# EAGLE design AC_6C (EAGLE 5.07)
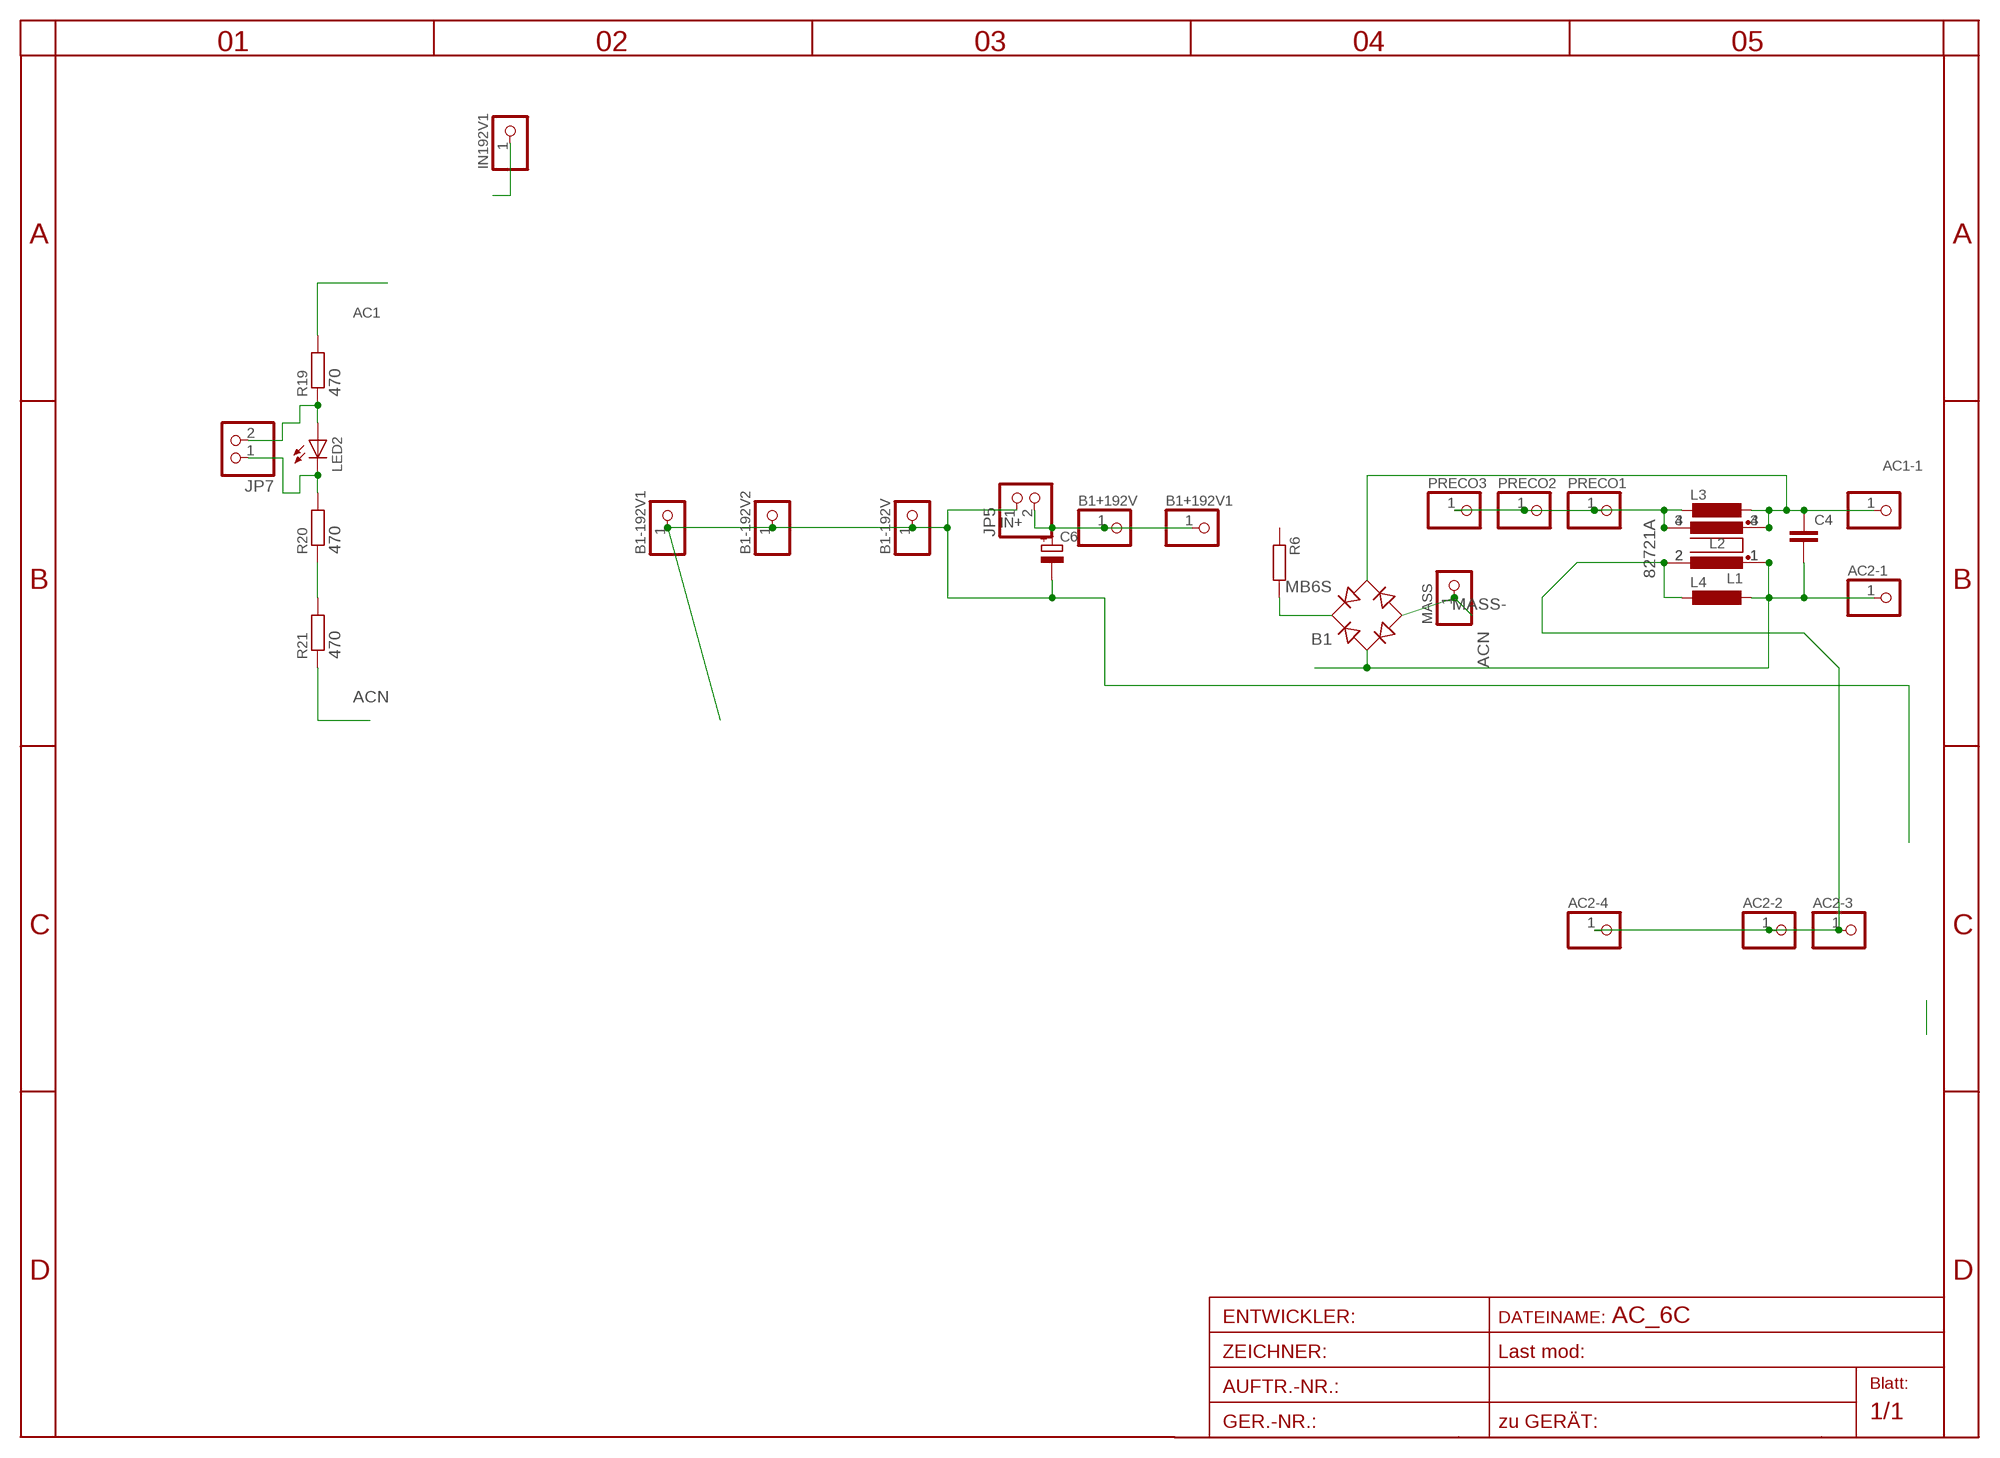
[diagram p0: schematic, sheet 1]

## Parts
AC1-1  PINHD-1X14.5MM  [1X4MM5]
AC2-1  PINHD-1X14.5MM  [1X4MM5]
AC2-2  PINHD-1X13MM2  [1X3MM2]
AC2-3  PINHD-1X13MM2  [1X3MM2]
AC2-4  PINHD-1X12MM3  [1X2MM3]
B1  MB6S  [SOIC-4]
B1+192V  PINHD-1X13MM2  [1X3MM2]
B1+192V1  PINHD-1X13MM2  [1X3MM2]
B1-192V  PINHD-1X13MM2  [1X3MM2]
B1-192V1  PINHD-1X13MM2  [1X3MM2]
B1-192V2  PINHD-1X13MM2  [1X3MM2]
C4  C-EU102-043X133  [C102-043X133]
C6  CPOL-EUE10-20  [EB20D]
IN192V1  PINHD-1X13MM2  [1X3MM2]
JP5  PINHD-1X2STR  [1X02]
JP7  PINHD-1X2STR  [1X02]
L1  R1405VB1  [B1]
L2  82721A  [82721A]
L3  L-EU2200-15.24  [2200-15.24]
L4  L-EU2200-15.24  [2200-15.24]
LED2  LED3MM  [LED3MM]
MASS  PINHD-1X13MM2  [1X3MM2]
PRECO1  PINHD-1X12MM3  [1X2MM3]
PRECO2  PINHD-1X13MM2  [1X3MM2]
PRECO3  PINHD-1X13MM2  [1X3MM2]
R6  R-EU_0207/60  [0207/60]
R19  470  R-EU_0204/5  [0204/5]
R20  470  R-EU_0204/2V  [0204V]
R21  470  R-EU_0204/5  [0204/5]

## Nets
AC1: AC1-1.1 B1.~2(AC2) C4.1 L1.3 L2.4 L3.1 R19.2
ACN: AC2-1.1 B1.~1(AC1) C4.2 L1.1 L2.1 L4.1 R21.1
IN+: B1+192V1.1 B1+192V.1 C6.+ IN192V1.1 JP5.2
INN: AC2-2.1 AC2-3.1 AC2-4.1 L1.2 L2.2 L4.2
MASS-: B1-192V1.1 B1-192V2.1 B1-192V.1 B1.- C6.- JP5.1 MASS.1
N$6: JP7.2 LED2.A R19.1
N$9: JP7.1 LED2.K(C) R20.2
N$13: R20.1 R21.2
N$33: B1.+ R6.2
PRECOIL: L1.4 L2.3 L3.2 PRECO1.1 PRECO2.1 PRECO3.1
Unconnected: R6.1

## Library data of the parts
AC1-1 AC2-1-AC2-4 B1+192V B1+192V1 B1-192V B1-192V1 B1-192V2 IN192V1 MASS PRECO1-PRECO3 = pinhead:PINHD-1X1: PIN HEADER
B1 = rectifier:MB*S: Bridge Rectifier Source: http://www.fairchildsemi.com/ds/MB/MB6S.pdf
C4 = rcl:C-EU: CAPACITOR, European symbol
C6 = rcl:CPOL-EU: POLARIZED CAPACITOR, European symbol
JP5 JP7 = pinhead:PINHD-1X2: PIN HEADER
L1 = inductor-nkl:R1405V: Übertrager (verlustarm) bis typ. 400kHz Power transformer (low loss) up to typ. 400kHz
L2 = inductors:82721A: FILTER
L3 L4 = rcl:L-EU: INDUCTOR, European symbol
LED2 = led:LED: LED
R6 R19-R21 = rcl-2:R-EU_: RESISTOR, European symbol

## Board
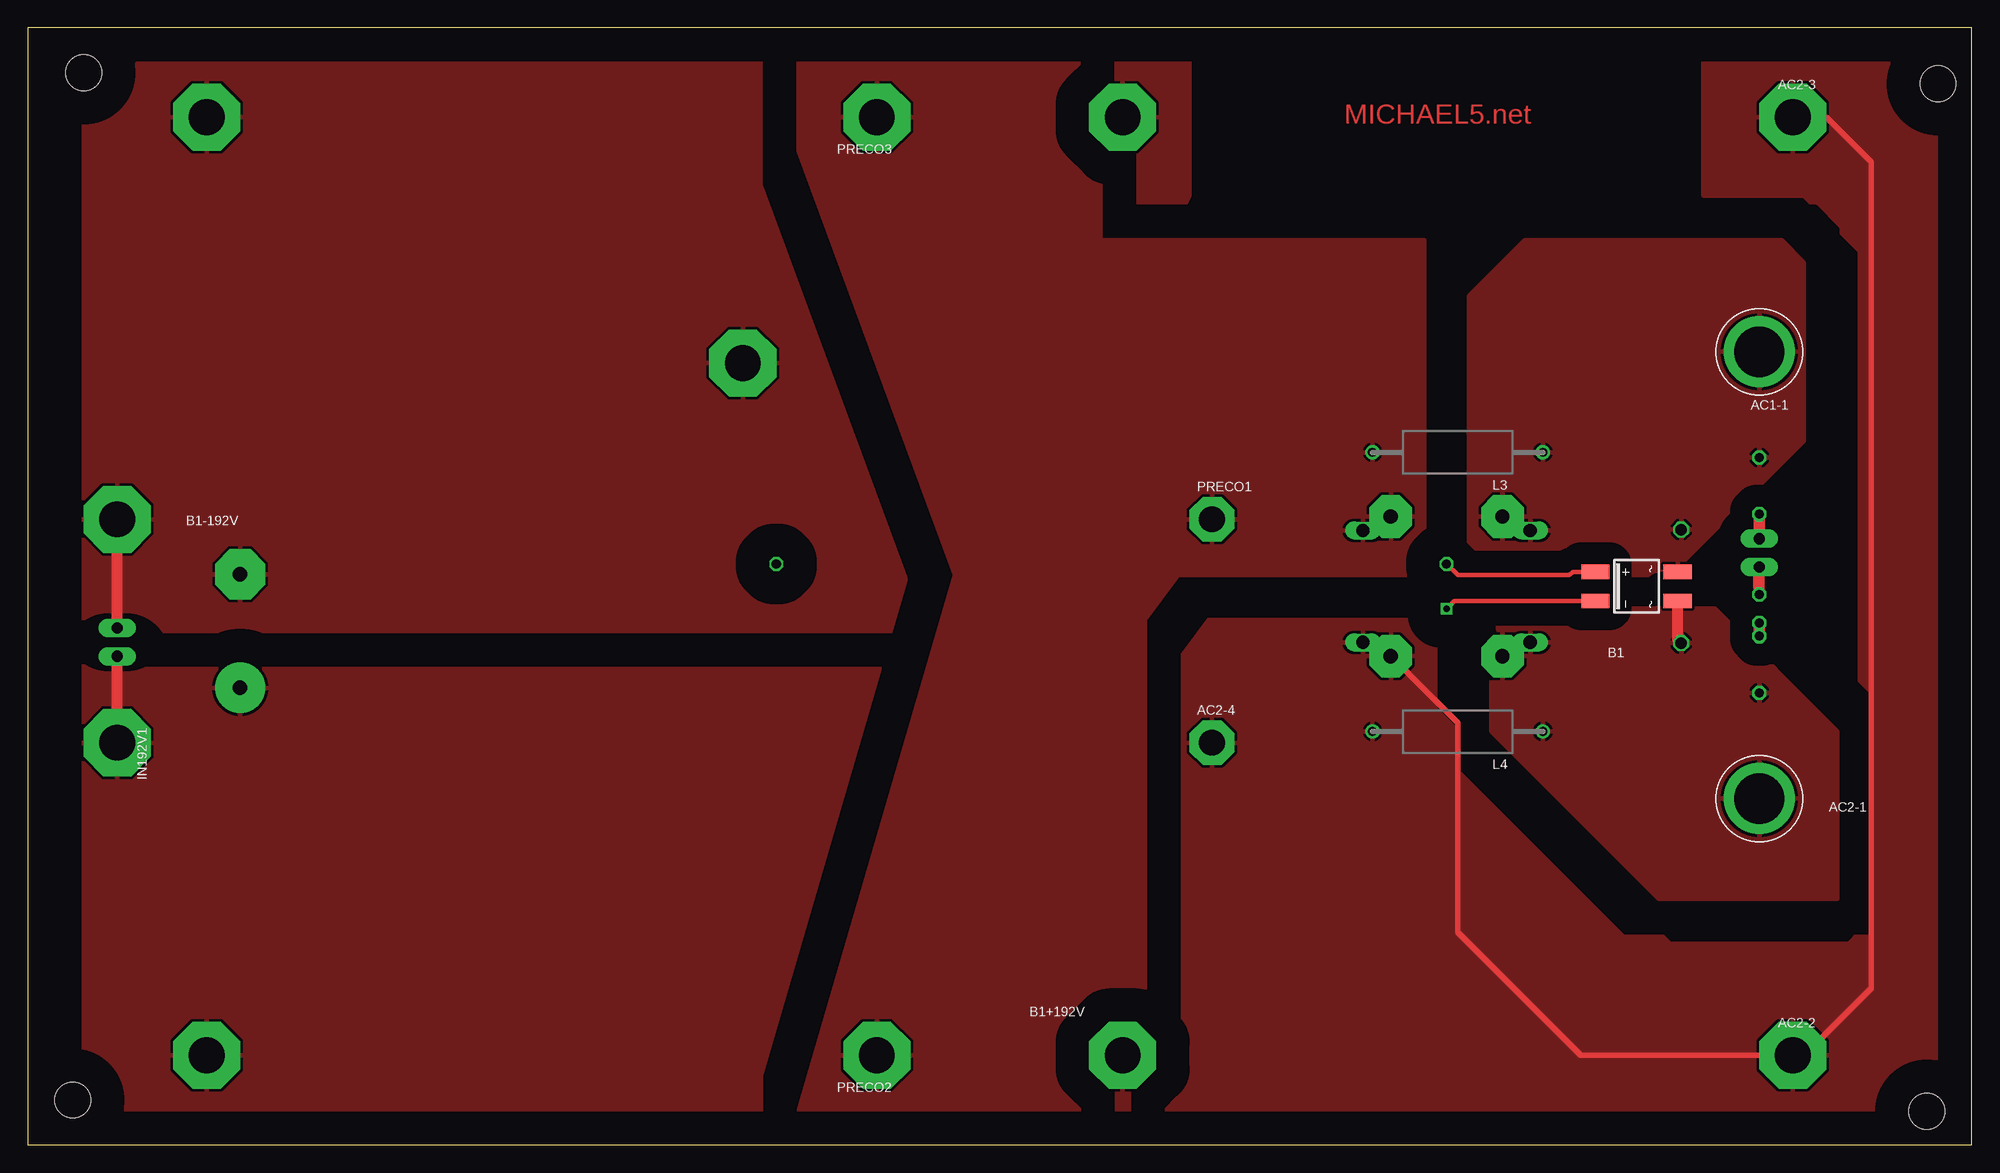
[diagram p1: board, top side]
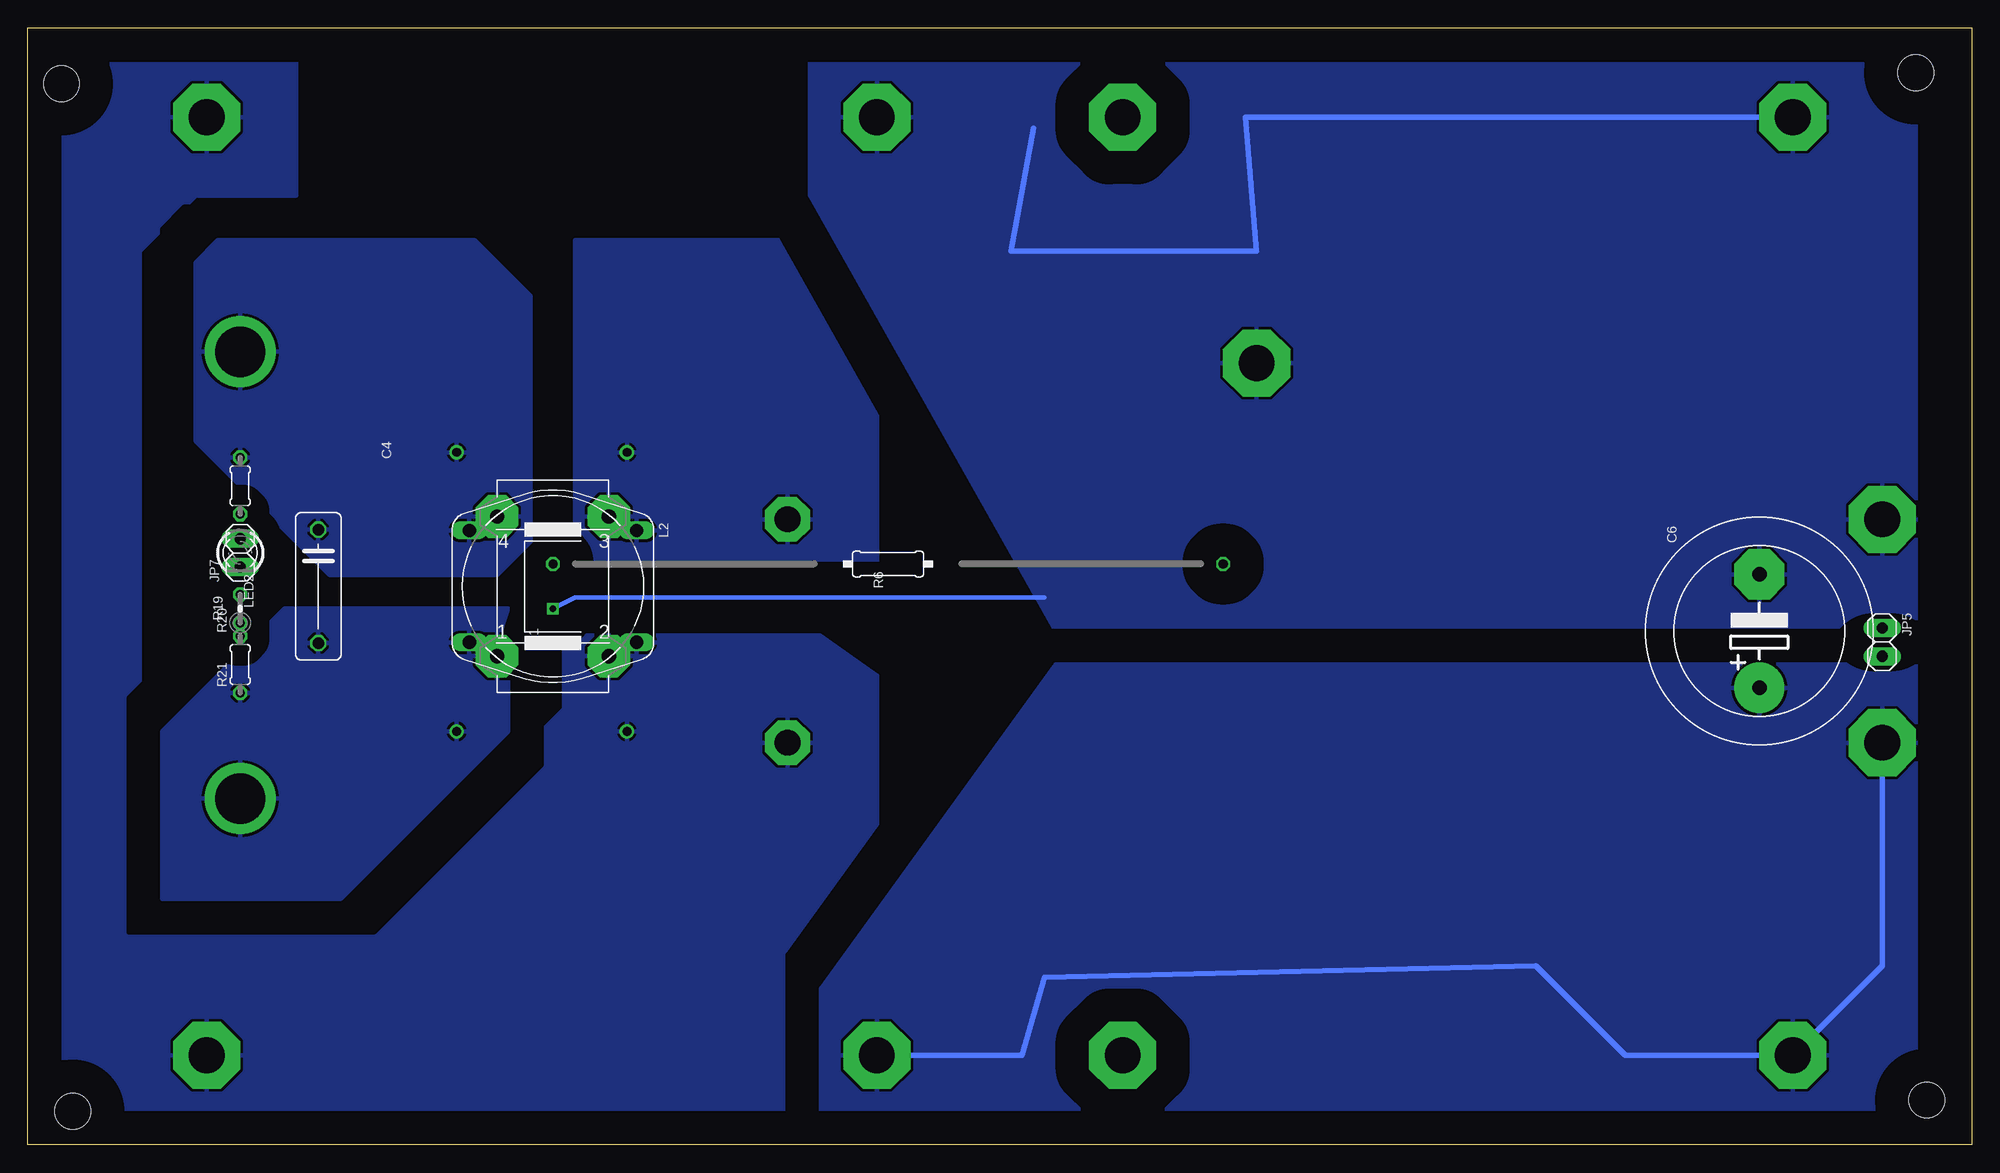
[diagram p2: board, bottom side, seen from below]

Size 174 x 100 mm. Coordinates in mm from the lower left corner, seen from the top.
Outline: 0,0 174,0 174,100 0,100 0,0
Copper layers (1*16): Top 0.035mm / dielectric 1.5mm / Bottom 0.035mm
Design rules "default *": minimum track width 12mil, minimum drill 24mil, track to track 8mil, track to pad 8mil, pad to pad 8mil, via to via 8mil, smd to smd 8mil, copper to edge 40mil, drill to drill 8mil, minimum pad ring 8mil, minimum via ring 8mil, stop-mask expansion 4mil, vias tented up to drill 0mil, thermal gap 10mil
Holes 3.2 mm at 5,96 4,4 171,95 170,3

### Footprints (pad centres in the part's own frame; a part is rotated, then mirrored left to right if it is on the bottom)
1X4MM5 = drill 4.5 pad 6.35 round: 1 0,0
1X3MM2 = drill 3.2 pad 6 octagon: 1 0,0
1X2MM3 = drill 2.3 pad 4 octagon: 1 0,0
SOIC-4 = smd 1.27 x 2.54: + 1.3,3.685; - -1.3,3.685; ~1 -1.3,-3.685; ~2 1.3,-3.685
C102-043X133 = drill 1.016 octagon: 1 -5.08,0; 2 5.08,0
EB20D = drill 1.3 pad 4.5 round: + -5.08,0 | drill 1.3 pad 4.5 octagon: - 5.08,0
1X02 = drill 1.016 pad 1.676 long: 1 -1.27,0; 2 1.27,0
B1 = drill 1.27 pad 3.81 octagon: 1 -6.25,5; 2 -6.25,-5; 3 6.25,5; 4 6.25,-5
82721A = drill 1.194 long: 1 7.493,5.004; 2 -7.493,5.004; 3 -7.493,-5.004; 4 7.493,-5.004
2200-15.24 = drill 0.8 pad 1.27 round: 1 -7.62,0; 2 7.62,0
LED3MM = drill 0.8 pad 1.27 octagon: A -1.27,0; K 1.27,0
0207/60 = drill 0.813 octagon: 1 -30,0; 2 30,0
0204/5 = drill 0.8 pad 1.27 octagon: 1 -2.54,0; 2 2.54,0
0204V = drill 0.8 pad 1.27 octagon: 1 -1.27,0; 2 1.27,0

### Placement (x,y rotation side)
AC1-1  155,71 180 top
AC2-1  155,31 180 top
AC2-2  158,8 0 top
AC2-3  158,92 0 top
AC2-4  106,36 0 top
B1  144,50 90 top
B1+192V  98,8 0 top
B1+192V1  16,8 0 top
B1-192V  8,56 180 top
B1-192V1  16,92 180 top
B1-192V2  98,92 0 top
C4  148,50 270 bottom
C6  19,46 90 bottom
IN192V1  8,36 270 top
JP5  8,45 270 bottom
JP7  155,53 90 bottom
L1  127,50 90 bottom
L2  127,50 180 bottom
L3  128,62 180 top
L4  128,37 180 top
LED2  155,53 270 bottom
MASS  64,70 0 top
PRECO1  106,56 0 top
PRECO2  76,8 180 top
PRECO3  76,92 180 top
R6  97,52 180 bottom
R19  155,59 90 bottom
R20  155,48 90 bottom
R21  155,43 90 bottom

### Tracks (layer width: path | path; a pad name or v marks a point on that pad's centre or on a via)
AC1
  pour Bottom (isolate 2): 129,76 129,54 132,51 147,51 159,63 159,79 157,81 134,81
  pour Top (isolate 2): 129,76 129,54 132,51 147,51 159,63 159,79 157,81 134,81
ACN
  Top 1: B1.~1 147.69,45.23 C4.2
  pour Bottom (isolate 2, rank 2): 131,48 151,48 162,37 162,22 146,22 131,37 131,44 132,45
  pour Top (isolate 2, rank 2): 131,48 151,48 162,37 162,22 146,22 131,37 131,44 132,45
IN+
  Top 1: IN192V1.1 JP5.2
  Bottom 0.5: B1+192V.1 85,8 83,15 39,16 31,8 B1+192V1.1 8,16 IN192V1.1
  pour Bottom (isolate 3): 5,2 5,43 82,43 103,14 103,2
  pour Top (isolate 3, rank 4): 5,2 5,43 82,43 103,14 103,2
INN
  Top 0.5: AC2-3.1 161,92 165,88 165,14 158,7 157,8 | L1.2 128,37.75 128,19 139,8 AC2-2.1
  pour Top (isolate 3, rank 3): 150,97 172,97 172,2 100,2 100,42 105,47 124,47 126,45 126,39 147,18 163,18 164,19 164,80 159,85 150,85
  pour Bottom (isolate 3, rank 3): 150,97 172,97 172,2 98,2 98,42 105,47 124,47 126,45 126,39 146,19 164,19 164,80 159,85 150,85
MASS-  (via drill 0.6)
  Top 0.406: B1.- 127.7,48.7 v127,48
  Top 1: JP5.1 B1-192V.1
  Bottom 0.406: v127,48 125,49 83,49
  Bottom 0.5: B1-192V1.1 65,92 64,80 86,80 84,91
  pour Bottom (isolate 3, rank 2): 5,46 82,46 104,85 104,97 10,97 5,92
  pour Top (isolate 3, rank 3): 5,46 83,46 104,85 104,97 10,97 5,92
N$6
  Top 1.016: JP7.2 R19.1
N$9
  Top 1.016: R20.2 154.96,50.27 JP7.1
N$13
  Top 1.016: R21.2 R20.1
N$33
  Top 0.406: B1.+ 138.3,51.3 138,51 128,51 R6.2
PRECOIL
  pour Top (isolate 3, rank 2): 69,98 93,98 96,95 96,81 125,81 125,51 103,51 100,47 100,5 98,3 69,3 83,51 69,89
  pour Bottom (isolate 3, rank 5): 98,45 98,74 102,81 125,81 125,45

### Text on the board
Top: MICHAEL5.net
